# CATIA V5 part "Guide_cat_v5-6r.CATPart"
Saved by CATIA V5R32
Part number: Guide
Bounding box of the stored display mesh (mm): x -25 to 25, y -50 to 25, z -10 to 10
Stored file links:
  D:\PROJECTS\Project 2022\CATIA V5 6R 2022\Resources\Tutorial Files\c16_catia_v5_6r2022_tut\Slide Curve\Guide_cat_v5-6r.CATPart
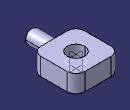
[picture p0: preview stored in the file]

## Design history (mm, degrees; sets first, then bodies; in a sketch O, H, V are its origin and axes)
Body1 (main body)
  Sketch1 on xy-plane, origin (0, 0, 0), H (1, 0, 0), V (0, 1, 0)
    circle A1 centre (0, 0) radius 10
    line L1 (-25, 25) -> (25, 25)
    line L2 (25, 25) -> (25, -25)
    line L3 (25, -25) -> (-25, -25)
    line L4 (-25, -25) -> (-25, 25)
    radius A1 = 10
    length L4 = 50
    length L3 = 50
    distance V L4 = 25
    distance L3 H = 25
    horizontal: L1 H, L3 H
    vertical: L2 V, L4 V
  Pad1: profile Sketch1, direction (0, 0, 1), length 10, mirrored extent
  Sketch2 on face of Pad1 from Sketch1.L3, origin (0, -25, 0), H (1, 0, 0), V (0, 0, 1)
    circle A1 centre (0, 0) radius 7.5
    point P1 (0, 0)
    reference projected line E1 (-25, 10) -> (25, 10) from edge [face of Pad1 from Sketch1.L3 | end face of Pad1]
    radius A1 = 7.5
    distance E1 P1 = 10
    coincidence: P1 V
  Pad2: profile Sketch2, direction (0, -1, 0), length 25
  Fillet1: radius 10, on edge [face of Pad1 from Sketch1.L2 | face of Pad1 from Sketch1.L3]; edge [face of Pad1 from Sketch1.L3 | face of Pad1 from Sketch1.L4]; edge [face of Pad1 from Sketch1.L1 | face of Pad1 from Sketch1.L2]; edge [face of Pad1 from Sketch1.L4 | face of Pad1 from Sketch1.L1]
  Fillet2: radius 2, on edge [face of Pad1 from Sketch1.L3 | face of Pad2 from Sketch2.A1]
